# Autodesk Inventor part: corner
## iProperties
Shininess: 64.0
Length Units: 11269
Angle Units: 11279
Time Units: 11290
Mass Units: 11283
Length Display Precision: 3
Angle Display Precision: 2
Compacted: True
Part Number: corner
Document SubType Name: Modeling
Created: 2004-10
Material: Standard
Designer: W. Holzwarth
Manufacturer: Standard
Standards Organization: Custom
Density: 0.0
Volumn: 0.0
Area: 0.0
PropertySet Name: Model Information
Control State: 0
Master: False
Checked Out: False
Author: W. Holzwarth
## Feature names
1. Basis1
